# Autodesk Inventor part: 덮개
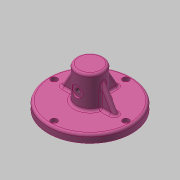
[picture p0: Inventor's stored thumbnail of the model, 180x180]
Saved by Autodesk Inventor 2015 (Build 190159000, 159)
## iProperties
Created: 2017-08
Part Number: 덮개
Material: 알루미늄 6061
Document SubType Name: Modeling
Designer: mduedu
Density: 2.71 g/cm^3
Mass: 336.253 g
Surface Area: 314.323 cm^2
Volume: 124.078 cm^3
Appearance: 분홍색
Author: mduedu
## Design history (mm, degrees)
sketch "스케치1"
  geometry: C1 r 52.5 at (0, 0); 1 further point
  constraints: 1 centre point, 1 coincident
  dimensions: "d55" = 105 diameter of C1
extrude "돌출1" new body sketch "스케치1" distance "d5" = 10; taper "d6" = 0 deg
sketch "스케치2"
  geometry: C1 r 17 at (0, 0); 1 further point
  constraints: 1 centre point, 1 coincident
  dimensions: "d74" = 34 diameter of C1
extrude "돌출2" join sketch "스케치2" distance "d9" = 40; taper "d10" = 0 deg
sketch "스케치3"
  geometry: C1 r 37 at (0, 0); 1 further point
  constraints: 1 centre point, 1 coincident
  dimensions: "d56" = 74 diameter of C1
extrude "돌출3" join sketch "스케치3" distance "d12" = 8; taper "d13" = 0 deg
sketch "스케치4"
  geometry: C1 r 33 at (0, 0); 1 further point
  constraints: 1 centre point, 1 coincident
  dimensions: "d57" = 66 diameter of C1
extrude "돌출4" cut sketch "스케치4" distance "d16" = 7; taper "d17" = 0 deg
sketch "스케치5"
  geometry: C1 r 9 at (0, 0); 1 further point
  constraints: 1 centre point, 1 coincident
  dimensions: "d18" = 18 diameter of C1
extrude "돌출5" cut sketch "스케치5" distance "d19" = 47; taper "d20" = 0 deg
node "작업 평면1"
sketch "스케치11"
  geometry: L1 (-52.5, -10)-(52.5, -10) reference; 2 further points
  constraints: 1 vertical alignment
  dimensions: "d78" = 28 distance from line of point (0, 18) L1
hole "구멍5" sketch "스케치11" at (0, 18) diameter "d79" = 5.917; stored, may be unused: countersink angle "d83" = 90 deg, drill point angle "d85" = 118 deg; dims "d80" = 6, "d81" = 14, "d82" = 2, "d84" = 8
fillet "모깎기9" dims "d86" = 3
fillet "모깎기5" dims "d40" = 1
sketch "스케치12"
  geometry: C1 r 2.5 at (0, 0); 1 further point
  constraints: 1 centre point, 1 coincident
  dimensions: "d87" = 5 diameter of C1
extrude "돌출6" join sketch "스케치12" distance "d88" = 3; taper "d89" = 0 deg
fillet "모깎기10" dims "d91" = 1
chamfer "모따기1" distance "d41" = 1; stored, may be unused: second distance "d42" = 2, angle "d43" = 45 deg
fillet "모깎기7" dims "d45" = 3
fillet "모깎기8" dims "d46" = 3
sketch "스케치10" dims "d59" = 90
  geometry: 3 further points
  constraints: 2 vertical alignment, 1 coincident, 2 other
hole "구멍4" sketch "스케치10" at (0, 45) diameter "d60" = 4.5; stored, may be unused: countersink angle "d64" = 90 deg, drill point angle "d66" = 118 deg; dims "d61" = 6, "d62" = 8, "d63" = 4.6, "d65" = 8
sketch "스케치13"
  geometry: L1 (52.5, 7)-(52.5, 0) reference; L2 (52.5, 0)-(47.25, 0) reference; L3 (47.25, 0)-(47.25, 5.4) reference; L4 (47.25, 5.4)-(49, 5.4) reference; L5 (49, 5.4)-(49, 10) reference; L6 (49, 10)-(49.5, 10) reference; L7 (-49.5, 10)-(-49, 10) reference; L8 (-49, 10)-(-49, 5.4) reference; L9 (-49, 5.4)-(-47.25, 5.4) reference; L10 (-47.25, 5.4)-(-47.25, 0) reference; L11 (-47.25, 0)-(-52.5, 0) reference; L12 (-52.5, 0)-(-52.5, 7) reference; L13 (-3.5, 46)-(-8, 46) reference; L14 (-9, 45)-(-9, -1) reference; L15 (-9, -1)-(-30, -1) reference; L16 (-33, -4)-(-33, -8) reference; L17 (-33, -8)-(-36, -8) reference; L18 (-36, -8)-(-37, -7) reference; L19 (-37, -7)-(-37, 0) reference; L20 (-37, 0)-(-42.75, 0) reference; L21 (-42.75, 0)-(-42.75, 5.4) reference; L22 (-42.75, 5.4)-(-41, 5.4) reference; L23 (-41, 5.4)-(-41, 10) reference; L24 (-41, 10)-(-20, 10) reference; L25 (-17, 13)-(-17, 47) reference; L26 (-14, 50)-(14, 50) reference; L27 (17, 47)-(17, 13) reference; L28 (20, 10)-(41, 10) reference; L29 (41, 10)-(41, 5.4) reference; L30 (41, 5.4)-(42.75, 5.4) reference; L31 (42.75, 5.4)-(42.75, 0) reference; L32 (42.75, 0)-(37, 0) reference; L33 (37, 0)-(37, -7) reference; L34 (37, -7)-(36, -8) reference; L35 (36, -8)-(33, -8) reference; L36 (33, -8)-(33, -4) reference; L37 (30, -1)-(9, -1) reference; L38 (9, -1)-(9, 45) reference; L39 (8, 46)-(3.5, 46) reference; L40 (2.5, 45)-(2.5, 43) reference; L41 (2.5, 43)-(-2.5, 43) reference; L42 (-2.5, 43)-(-2.5, 45) reference; L43 (17, 40)-(34.321, 10); L44 (-49.5, 10)-(49.5, 10) reference; A1 r 3 centre (49.5, 7) between (52.5, 7) and (49.5, 10) reference; A2 r 3 centre (-49.5, 7) between (-49.5, 10) and (-52.5, 7) reference; A3 r 1 centre (-3.5, 45) between (-2.5, 45) and (-3.5, 46) reference; A4 r 1 centre (-8, 45) between (-8, 46) and (-9, 45) reference; A5 r 3 centre (-30, -4) between (-30, -1) and (-33, -4) reference; A6 r 3 centre (-20, 13) between (-20, 10) and (-17, 13) reference; A7 r 3 centre (-14, 47) between (-14, 50) and (-17, 47) reference; A8 r 3 centre (14, 47) between (17, 47) and (14, 50) reference; A9 r 3 centre (20, 13) between (17, 13) and (20, 10) reference; A10 r 3 centre (30, -4) between (33, -4) and (30, -1) reference; A11 r 1 centre (8, 45) between (9, 45) and (8, 46) reference; A12 r 1 centre (3.5, 45) between (3.5, 46) and (2.5, 45) reference; 1 further point
  constraints: 2 end point, 2 point on line
  dimensions: "d98" = 120 deg angle of L43 L28; "d99" = 30 distance from line of L43.start L44
feature "리브1" sketch "스케치13" dims "d100" = 1, "d101" = 6, "d102" = 0, "d103" = 0, "d104" = 1, "d105" = 1
fillet "모깎기11" dims "d106" = 3
fillet "모깎기12" dims "d107" = 3
node "솔리드1"
pattern_circular "원형 패턴1" dims angle "d68" = 360 deg
pattern_circular "원형 패턴2" dims "d109" = 270 deg
node "절단 모서리 투영1"
